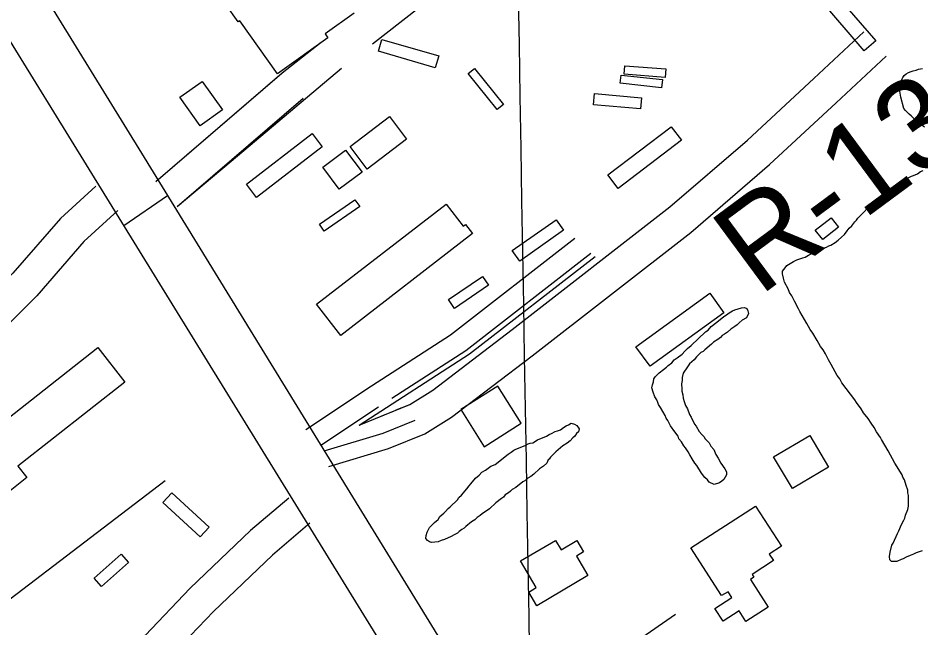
# Model space of a CAD drawing. Extents: x 3892998 to 3931244, y 278583 to 304547.
# Drawn here: x 3901838 to 3902660, y 300286 to 300842 of the extents above; entities that cross this region are included whole.
import ezdxf

# ---------------------------------------------------------------- set-up
doc = ezdxf.new("R2010")
doc.units = 0
for name, color, linetype in [('V-BLDG-OTLN', 7, 'Continuous'), ('V-GRID-MAJR', 7, 'Continuous'), ('V-RIVR-EDGE', 7, 'Continuous'), ('V-RIVR-RANG-IDEN', 7, 'Continuous'), ('V-ROAD-CNTR', 7, 'Continuous'), ('V-SITE-VEGE', 7, 'Continuous'), ('V-TOPO-SHOR', 7, 'Continuous')]:
    doc.layers.add(name, color=color, linetype=linetype)

msp = doc.modelspace()

# ---------------------------------------------------------------- linework, layer by layer
at = {"layer": 'V-BLDG-OTLN'}
for points in [[(3902578.335, 300868.101), (3902618.843, 300820.995), (3902608.369, 300811.992), (3902567.864, 300859.096)], [(3902169.247, 300822.322), (3902220.916, 300807.286), (3902217.7460000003, 300796.388), (3902166.077, 300811.422)], [(3902253.3710000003, 300795.72000000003), (3902279.958, 300763.014), (3902274.269, 300758.39), (3902247.682, 300791.096)], [(3902427.1010000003, 300787.664), (3902389.782, 300790.656), (3902390.399, 300798.332), (3902427.717, 300795.337)], [(3902005.5100000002, 300783.951), (3902023.952, 300758.068), (3902003.734, 300743.662), (3901985.292, 300769.543)], [(3902423.795, 300778.278), (3902386.1040000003, 300782.458), (3902386.919, 300789.824), (3902424.612, 300785.642)], [(3902404.585, 300758.936), (3902361.776, 300762.80700000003), (3902362.683, 300772.855), (3902405.494, 300768.976)], [(3902191.704, 300731.467), (3902155.8370000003, 300704.146), (3902140.242, 300724.62), (3902176.106, 300751.942)], [(3902374.852, 300698.86), (3902432.634, 300742.726), (3902441.957, 300730.447), (3902384.1750000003, 300686.583)], [(3902114.879, 300724.507), (3902055.092, 300678.317), (3902045.778, 300690.371), (3902105.5670000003, 300736.564)], [(3902136.0700000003, 300721.39400000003), (3902151.071, 300701.474), (3902130.3310000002, 300685.853), (3902115.33, 300705.776)], [(3902109.696, 300581.018), (3902227.677, 300672.24700000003), (3902243.1580000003, 300652.227), (3902245.187, 300653.79600000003), (3902251.673, 300645.408), (3902131.66, 300552.613)], [(3902148.966, 300670.039), (3902116.7260000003, 300647.771), (3902112.417, 300654.007), (3902144.657, 300676.279)], [(3902287.931, 300629.923), (3902327.742, 300657.964), (3902334.443, 300648.449), (3902294.63, 300620.412)], [(3902584.889, 300651.246), (3902570.539, 300640.081), (3902563.838, 300648.695), (3902578.19, 300659.858)], [(3902229.7430000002, 300585.276), (3902260.7830000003, 300606.387), (3902266.267, 300598.322), (3902235.23, 300577.215)], [(3902400.522, 300542.26), (3902467.827, 300591.076), (3902480.662, 300573.379), (3902413.3570000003, 300524.563)], [(3901736.147, 300404.54600000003), (3901910.3680000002, 300541.631), (3901935.075, 300510.231), (3901837.596, 300433.532), (3901845.698, 300423.234), (3901815.079, 300399.142), (3901819.856, 300393.067), (3901773.733, 300356.777)], [(3902240.9494783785, 300485.219004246), (3902262.241435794, 300451.35707197), (3902296.10336807, 300472.6480293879), (3902274.812410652, 300506.5109616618)], [(3902525.884, 300442.189), (3902558.863, 300461.692), (3902575.9390000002, 300432.811), (3902542.958, 300413.31200000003)], [(3901977.753, 300409.5), (3902011.84, 300378.24), (3902003.6750000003, 300369.337), (3901969.59, 300400.598)], [(3902450.526, 300359.283), (3902509.3850000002, 300397.231), (3902532.966, 300360.654), (3902521.909, 300353.527), (3902525.728, 300347.60000000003), (3902506.326, 300335.092), (3902507.991, 300332.51), (3902504.7320000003, 300330.409), (3902520.989, 300305.192), (3902500.694, 300292.105), (3902494.441, 300301.8), (3902479.9760000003, 300292.476), (3902472.4620000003, 300304.13300000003), (3902487.765, 300313.998), (3902484.346, 300319.302), (3902478.4560000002, 300315.958)], [(3902295.339, 300347.36), (3902327.1240000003, 300366.097), (3902332.276, 300357.356), (3902346.809, 300365.923), (3902352.865, 300355.652), (3902346.342, 300351.806), (3902356.805, 300334.052), (3902310.166, 300306.558), (3902302.853, 300318.964), (3902309.697, 300323.001)], [(3901938.522, 300346.043), (3901913.761, 300324.044), (3901907.112, 300331.529), (3901931.876, 300353.527)]]:
    msp.add_lwpolyline(points, close=True, dxfattribs=at)
msp.add_lwpolyline([(3902143.846, 300846.118), (3902117.4390000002, 300827.39900000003), (3902120.044, 300823.723), (3902073.97, 300791.061), (3902039.7830000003, 300839.288), (3902038.321, 300838.249), (3902027.071, 300854.119)], dxfattribs=at)
at = {"layer": 'V-GRID-MAJR'}
msp.add_spline([(3902578.647, 284107.213), (3902475.546, 290165.246), (3902372.4110000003, 296225.205), (3902269.2770000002, 302285.157), (3902269.244, 302287.088)], degree=3, dxfattribs=at)
at = {"layer": 'V-RIVR-EDGE'}
msp.add_spline([(3901800.0009682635, 302280.7546799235), (3901821.3536927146, 302255.3367813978), (3901852.8284176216, 302218.3508038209), (3901878.4743747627, 302180.8936055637), (3901907.490926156, 302131.7728676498), (3901945.242823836, 302080.20236199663), (3901978.6384562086, 302034.47023070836), (3902005.7497108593, 302000.40884402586), (3902060.9446821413, 301932.7692995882), (3902101.618769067, 301884.5910030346), (3902148.1024105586, 301829.1138379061), (3902188.290866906, 301780.93674217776), (3902273.0180407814, 301676.31602346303), (3902336.4471170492, 301599.91471459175), (3902373.2325568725, 301550.28913290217), (3902435.6603513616, 301461.74946121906), (3902481.158321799, 301400.44713079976), (3902498.0821417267, 301370.7816366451), (3902573.5883387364, 301268.6118864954), (3902614.7276422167, 301212.17666928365), (3902639.8879687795, 301174.72067185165), (3902676.667404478, 301122.66693726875), (3902702.325369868, 301090.06604479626), (3902717.8103104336, 301067.6886117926), (3902729.4438294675, 301058.91844158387), (3902740.5725047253, 301042.37938294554), (3902748.775388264, 301020.9912234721), (3902799.0972422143, 300946.5648591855), (3902823.275500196, 300904.740588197), (3902856.184301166, 300858.5240271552), (3902877.4787962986, 300828.8477255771), (3902907.496629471, 300791.86535047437), (3902952.97778836, 300723.76419195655), (3902991.208111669, 300669.2787020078), (3903039.1222267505, 300603.1140616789), (3903064.7825937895, 300571.48443036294), (3903083.177715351, 300547.64290067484), (3903091.390205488, 300530.1397858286), (3903107.8428047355, 300506.3030594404), (3903122.8409138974, 300483.44119668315), (3903163.4957876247, 300427.49281087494), (3903201.7381191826, 300377.86362671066), (3903235.1409565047, 300335.0452788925), (3903245.7779970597, 300316.07926818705), (3903281.578966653, 300261.11415178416), (3903312.5572535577, 300219.758699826), (3903345.458849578, 300170.62835531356), (3903361.421014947, 300144.850307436), (3903395.2974745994, 300097.1744530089), (3903411.741668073, 300069.9383125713), (3903428.6450739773, 300032.0170985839), (3903446.529347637, 299997.9785275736), (3903470.239987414, 299963.43991608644), (3903493.458992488, 299926.4743525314), (3903530.2312232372, 299871.5068344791), (3903555.4035580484, 299838.9071428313), (3903589.2920259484, 299796.08759418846), (3903617.862573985, 299762.9938661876), (3903644.9762302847, 299729.90374066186), (3903672.0958907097, 299699.241768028), (3903702.082502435, 299649.6329978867), (3903724.349459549, 299620.4399252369), (3903758.2523373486, 299583.44794353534), (3903801.3557779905, 299535.74927343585), (3903821.2077912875, 299511.90414127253), (3903855.090255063, 299466.6564397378), (3903910.2744189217, 299394.6462200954), (3903941.2178819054, 299339.2074813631), (3903956.2147902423, 299315.85998802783), (3903981.8535424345, 299275.4890063), (3904009.437218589, 299236.08448243), (3904049.1448476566, 299189.8511098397), (3904076.74293371, 299156.27415291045)], degree=3, dxfattribs=at)
at = {"layer": 'V-ROAD-CNTR'}
for points in [[(3901475.414, 301488.89900000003), (3901950.21, 300718.639), (3902361.495, 300048.637), (3902781.22, 299367.234), (3903376.271, 298399.706), (3903987.162, 297400.843), (3904677.957, 296281.166)], [(3901495.955, 301363.439), (3902227.998, 300175.63), (3903253.1750000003, 298505.409), (3903985.838, 297316.44800000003), (3904685.844, 296169.052)], [(3902160.574, 300818.154), (3902231.134, 300873.402)], [(3902148.5530000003, 300471.12), (3902194.6210000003, 300489.843), (3902215.464, 300502.896), (3902287.648, 300557.985), (3902431.446, 300669.692), (3902502.093, 300730.617), (3902562.4280000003, 300786.62), (3902607.9560000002, 300829.023)], [(3902168.467, 300479.214), (3902194.6210000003, 300489.843), (3902215.464, 300502.896), (3902287.648, 300557.985), (3902431.446, 300669.692), (3902502.093, 300730.617), (3902562.4280000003, 300786.62), (3902607.9560000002, 300829.023)], [(3902182.291, 300484.832), (3902194.6210000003, 300489.843), (3902215.464, 300502.896), (3902287.648, 300557.985), (3902431.446, 300669.692), (3902502.093, 300730.617), (3902562.4280000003, 300786.62), (3902607.9560000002, 300829.023)], [(3901963.22, 300692.888), (3902078.304, 300791.84), (3902113.855, 300819.676)], [(3902120.877, 300433.273), (3902175.313, 300449.613), (3902208.333, 300463.033), (3902232.562, 300478.206), (3902305.95, 300534.215), (3902450.4560000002, 300646.472), (3902522.1010000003, 300708.257), (3902582.856, 300764.65), (3902628.4020000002, 300807.069)], [(3901982.778, 300670.14), (3902031.912, 300711.266), (3902132.349, 300796.056)], [(3901963.22, 300692.888), (3902078.043, 300791.616)], [(3901982.778, 300670.14), (3902097.6010000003, 300768.868)], [(3901908.65, 300688.516), (3901876.386, 300659.158), (3901833.023, 300609.264), (3901770.574, 300546.904), (3901650.615, 300452.341), (3901498.917, 300325.309)], [(3901973.9930000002, 300679.896), (3901934.056, 300652.578)], [(3901928.84, 300666.328), (3901897.876, 300638.152), (3901854.971, 300588.784), (3901790.528, 300524.43200000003), (3901669.535, 300429.055), (3901518.177, 300302.309)], [(3902099.808, 300466.898), (3902159.651, 300506.805), (3902231.64, 300553.159), (3902344.872, 300641.13)], [(3902148.5530000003, 300471.12), (3902248.9990000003, 300535.797), (3902363.279, 300624.582)], [(3902178.218, 300495.678), (3902245.6890000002, 300539.12200000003), (3902359.4450000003, 300627.5)], [(3902113.5, 300452.63300000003), (3902166.119, 300487.724)], [(3902116.565, 300447.64), (3902170.322, 300463.776), (3902199.355, 300475.576)], [(3902084.274, 300404.52400000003), (3902049.458, 300374.978), (3901994.637, 300322.4), (3901953.503, 300279.539), (3901923.348, 300254.061), (3901891.696, 300237.68), (3901832.664, 300200.05), (3901768.819, 300148.331), (3901719.525, 300103.481)], [(3902103.686, 300381.65), (3902069.5640000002, 300352.694), (3902015.8510000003, 300301.178), (3901974.061, 300257.635), (3901940.132, 300228.969), (3901906.684, 300211.658), (3901850.2260000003, 300175.668), (3901788.3710000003, 300125.561), (3901739.715, 300081.291)], [(3902275.473, 300187.178), (3902436.67, 300298.91000000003)]]:
    msp.add_lwpolyline(points, dxfattribs=at)
at = {"layer": 'V-SITE-VEGE'}
for points in [[(3902663.3910000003, 300742.366), (3902659.5360000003, 300745.161), (3902657.605, 300746.366), (3902655.68, 300747.95900000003), (3902651.08, 300752.721), (3902649.1550000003, 300754.314), (3902646.0870000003, 300757.48600000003), (3902644.559, 300759.465), (3902641.61, 300769.66000000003), (3902640.924, 300775.134), (3902640.963, 300777.47500000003), (3902641.393, 300779.81), (3902641.844, 300783.314), (3902642.663, 300785.64), (3902643.4760000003, 300787.578), (3902644.6780000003, 300789.509), (3902646.657, 300791.037), (3902648.627, 300792.173), (3902650.98, 300792.915), (3902652.944, 300793.66000000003), (3902655.688, 300794.395), (3902657.6520000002, 300795.141), (3902661.566, 300795.856)], [(3902544.8140000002, 300583.998), (3902542.5530000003, 300588.719), (3902540.265, 300591.879), (3902539.149, 300595.021), (3902535.7430000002, 300601.32), (3902535.022, 300604.84500000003), (3902533.918, 300608.767), (3902533.957, 300611.106), (3902536.3510000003, 300614.188), (3902537.951, 300616.502), (3902543.861, 300619.914), (3902547.009, 300621.42100000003), (3902549.7600000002, 300622.54600000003), (3902552.504, 300623.279), (3902554.468, 300624.026), (3902557.622, 300625.925), (3902559.586, 300626.67), (3902562.343, 300628.186), (3902567.057, 300630.054), (3902570.205, 300631.563), (3902574.131, 300633.058), (3902576.103, 300634.195), (3902578.065, 300634.942), (3902582.005, 300637.218), (3902584.776, 300639.511), (3902587.5530000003, 300642.196), (3902590.324, 300644.49), (3902592.725, 300647.961), (3902594.713, 300650.26900000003), (3902597.095, 300652.571), (3902599.884, 300656.03500000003), (3902601.472, 300657.569), (3902602.676, 300659.5), (3902604.267, 300661.423), (3902608.234, 300665.259), (3902611.019, 300668.333), (3902612.613, 300670.25800000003), (3902616.58, 300674.092), (3902619.342, 300675.996), (3902620.936, 300677.92), (3902630.821, 300685.556), (3902634.768, 300688.221), (3902636.744, 300689.749), (3902640.2830000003, 300691.25), (3902643.441, 300693.538), (3902645.805, 300694.668), (3902651.318, 300697.695), (3902653.282, 300698.443), (3902656.819, 300699.944), (3902659.5840000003, 300701.848), (3902661.943, 300702.979)], [(3902661.144, 300356.484), (3902657.613, 300355.374), (3902655.649, 300354.626), (3902653.29, 300353.496), (3902650.148, 300352.378), (3902646.612, 300350.876), (3902643.855, 300349.363), (3902641.893, 300348.615), (3902637.957, 300346.731), (3902633.275, 300346.809), (3902631.741, 300348.396), (3902631.4050000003, 300351.526), (3902631.862, 300355.419), (3902633.5270000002, 300361.635), (3902634.7290000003, 300363.566), (3902638.782, 300372.471), (3902639.992, 300374.793), (3902642.434, 300380.603), (3902644.451, 300384.472), (3902645.264, 300386.409), (3902646.089, 300389.127), (3902648.123, 300394.165), (3902648.569, 300397.28), (3902648.733, 300407.031), (3902647.994, 300409.386), (3902648.0330000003, 300411.727), (3902646.546, 300416.044), (3902645.071, 300421.141), (3902643.5500000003, 300423.509), (3902642.81, 300425.862), (3902636.3570000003, 300436.507), (3902630.299, 300447.536), (3902624.231, 300457.784), (3902623.092, 300459.754), (3902619.668, 300464.884), (3902617.395, 300468.827), (3902614.728, 300472.773), (3902612.0700000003, 300477.11100000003), (3902607.865, 300482.256), (3902605.586, 300485.805), (3902601.394, 300491.73), (3902599.872, 300494.09500000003), (3902588.035, 300509.515), (3902586.146, 300513.06), (3902583.859, 300516.22000000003), (3902578.171, 300526.07300000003), (3902575.904, 300530.402), (3902573.267, 300535.909), (3902570.983, 300539.462), (3902568.697, 300542.62), (3902565.668, 300548.136), (3902561.491, 300554.839), (3902559.203, 300558.001), (3902556.174, 300563.514), (3902549.727, 300574.549), (3902548.596, 300576.91000000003), (3902544.8140000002, 300583.998)], [(3902481.3540000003, 300431.328), (3902482.87, 300428.571), (3902482.823, 300425.841), (3902481.612, 300423.521), (3902480.4080000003, 300421.59), (3902478.823, 300420.056), (3902476.4560000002, 300418.534), (3902471.747, 300417.053), (3902467.098, 300419.083), (3902465.572, 300421.061), (3902463.271, 300423.441), (3902460.217, 300427.396), (3902456.037, 300434.099), (3902454.126, 300436.473), (3902451.853, 300440.415), (3902449.571, 300443.964), (3902448.06, 300446.723), (3902445.776, 300450.272), (3902444.2490000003, 300452.248), (3902441.967, 300455.8), (3902439.673, 300458.571), (3902438.934, 300460.924), (3902435.879, 300464.88), (3902432.069, 300470.406), (3902429.417, 300475.13300000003), (3902427.897, 300477.5), (3902427.156, 300479.853), (3902424.875, 300483.405), (3902422.984, 300486.94800000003), (3902421.08, 300489.712), (3902420.332, 300491.676), (3902419.593, 300494.03), (3902417.688, 300496.792), (3902416.201, 300501.11), (3902415.095, 300505.031), (3902415.534, 300507.755), (3902416.3570000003, 300510.473), (3902416.795, 300513.197), (3902417.997, 300515.128), (3902419.984, 300517.045), (3902421.569, 300518.579), (3902425.524, 300521.635), (3902428.295, 300523.928), (3902429.88, 300525.462), (3902433.042, 300527.75), (3902435.4280000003, 300530.441), (3902438.193, 300532.346), (3902442.543, 300535.782), (3902444.929, 300538.473), (3902447.308, 300540.775), (3902450.866, 300543.44800000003), (3902463.9590000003, 300556.102), (3902466.324, 300557.62), (3902469.109, 300560.696), (3902474.254, 300564.903), (3902480.58, 300569.867), (3902482.95, 300571.389), (3902485.321, 300573.299), (3902488.475, 300575.19800000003), (3902490.437, 300575.943), (3902496.7120000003, 300577.789), (3902499.45, 300578.13300000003), (3902501.3880000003, 300577.32), (3902502.518, 300574.958), (3902502.867, 300572.61100000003), (3902501.242, 300568.737), (3902497.302, 300566.463), (3902494.531, 300564.167), (3902492.549, 300562.251), (3902490.5700000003, 300560.72500000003), (3902487.019, 300558.443), (3902483.853, 300555.764), (3902481.088, 300553.862), (3902479.12, 300552.723), (3902477.525, 300550.798), (3902475.153, 300548.887), (3902471.211, 300546.614), (3902469.228, 300544.695), (3902463.291, 300539.72500000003), (3902461.704, 300538.191), (3902459.734, 300537.054), (3902455.767, 300533.218), (3902453.379, 300530.527), (3902449.412, 300526.691), (3902447.415, 300523.996), (3902443.415, 300518.208), (3902442.569, 300514.32300000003), (3902442.522, 300511.591), (3902442.08, 300508.478), (3902442.397, 300504.179), (3902442.356, 300501.839), (3902443.085, 300498.703), (3902443.421, 300495.578), (3902444.537, 300492.436), (3902445.65, 300488.905), (3902447.548, 300485.752), (3902449.412, 300480.648), (3902450.933, 300478.28), (3902453.948, 300471.987), (3902455.4760000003, 300470.007), (3902458.128, 300465.282)], [(3902458.128, 300465.282), (3902460.4220000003, 300462.511), (3902462.339, 300460.52400000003), (3902463.477, 300458.556), (3902467.3170000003, 300454.98), (3902468.825, 300451.833), (3902471.503, 300448.666), (3902473.379, 300444.341), (3902475.272, 300440.798), (3902477.9280000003, 300436.458), (3902481.3540000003, 300431.328)]]:
    msp.add_lwpolyline(points, dxfattribs=at)
msp.add_lwpolyline([(3902341.578, 300472.718), (3902344.687, 300471.889), (3902346.616, 300470.68200000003), (3902348.906, 300467.522), (3902348.079, 300464.805), (3902346.491, 300463.271), (3902344.892, 300460.956), (3902342.916, 300459.429), (3902340.528, 300456.74), (3902337.759, 300454.444), (3902333.8140000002, 300452.168), (3902331.8340000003, 300450.252), (3902327.484, 300446.813), (3902325.897, 300445.279), (3902324.301, 300443.356), (3902322.716, 300441.822), (3902321.512, 300439.891), (3902320.7260000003, 300439.514), (3902319.503, 300436.413), (3902316.335, 300433.734), (3902312.7770000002, 300431.064), (3902307.627, 300426.468), (3902304.858, 300424.172), (3902302.099, 300422.661), (3902299.33, 300420.365), (3902297.36, 300419.228), (3902291.032, 300414.262), (3902287.878, 300412.364), (3902286.291, 300410.832), (3902284.312, 300409.304), (3902281.549, 300407.39900000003), (3902279.9560000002, 300405.478), (3902277.986, 300404.339), (3902272.841, 300400.13300000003), (3902267.289, 300394.765), (3902260.578, 300390.196), (3902258.602, 300388.668), (3902255.8370000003, 300386.764), (3902253.852, 300384.847), (3902250.698, 300382.94800000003), (3902245.556, 300378.744), (3902243.969, 300377.21), (3902241.9960000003, 300376.075), (3902239.625, 300374.162), (3902238.038, 300372.628), (3902235.674, 300371.498), (3902231.738, 300369.222), (3902229.383, 300368.481), (3902226.235, 300366.976), (3902223.095, 300365.858), (3902220.345, 300364.733), (3902214.4790000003, 300364.051), (3902212.542, 300364.864), (3902210.613, 300366.068), (3902209.079, 300367.656), (3902209.5130000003, 300370.38), (3902210.347, 300373.48600000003), (3902211.16, 300375.424), (3902212.37, 300377.742), (3902217.132, 300382.346), (3902220.298, 300385.025), (3902221.906, 300387.728), (3902225.467, 300390.792), (3902227.054, 300392.324), (3902229.4420000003, 300395.017), (3902231.418, 300396.543), (3902238.163, 300403.059), (3902239.367, 300404.993), (3902241.747, 300407.297), (3902246.5270000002, 300413.066), (3902248.523, 300415.763), (3902250.117, 300417.688), (3902254.491, 300422.685), (3902257.662, 300425.364), (3902260.0470000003, 300428.055), (3902263.593, 300429.946), (3902268.34, 300433.767), (3902272.268, 300435.262), (3902284.13, 300444.425), (3902286.893, 300446.33), (3902289.2660000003, 300448.24), (3902291.23, 300448.99), (3902293.59, 300450.116), (3902300.2660000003, 300452.738), (3902302.238, 300453.876), (3902304.202, 300454.62), (3902306.549, 300454.972), (3902310.887, 300457.63), (3902319.1380000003, 300461.001), (3902321.506, 300462.525), (3902323.47, 300463.271), (3902327.0130000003, 300465.161), (3902328.977, 300465.908), (3902331.721, 300466.64400000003), (3902334.49, 300468.93700000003), (3902336.856, 300470.457), (3902339.215, 300471.19800000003)], close=True, dxfattribs=at)
at = {"layer": 'V-TOPO-SHOR'}
msp.add_lwpolyline([(3901971.7260000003, 300420.226), (3901813.6920000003, 300299.906), (3901655.5130000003, 300171.189), (3901609.867, 300132.963), (3901587.245, 300113.947)], dxfattribs=at)

# ---------------------------------------------------------------- texts
at = {"layer": 'V-RIVR-RANG-IDEN'}
msp.add_text('R-13.8', height=82.99999800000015, rotation=36.46259877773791, dxfattribs=at).set_placement((3902512.882788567, 300587.66709604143))

doc.saveas('drawing.dxf')
